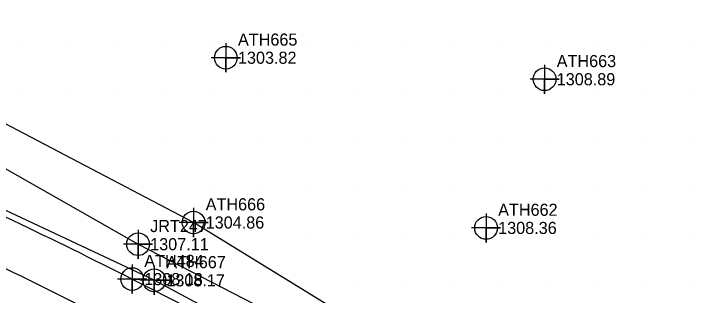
# Model space of a CAD drawing. Extents: x 1234484 to 1235382, y 695050 to 695510.
# Drawn here: x 1235159.5 to 1235304, y 695247.7 to 695305.7 of the extents above; entities that cross this region are included whole.
import ezdxf

# ---------------------------------------------------------------- set-up
doc = ezdxf.new("R2010")
doc.units = 0
for name, color, linetype in [('Exist DTM Breakline', 7, 'Continuous'), ('Exist DTM Breakline Cogo Elevation', 7, 'Continuous'), ('Exist DTM Breakline Cogo Number', 7, 'Continuous'), ('Exist DTM Breakline Cogo Point CELL', 7, 'Continuous'), ('Exist DTM Crownline', 7, 'Continuous'), ('Exist DTM QL2 LIDAR Elevation Point', 7, 'Continuous'), ('Exist DTM Regular Point CELL', 7, 'Continuous'), ('Exist DTM Regular Point Cogo Elevation', 7, 'Continuous'), ('Exist DTM Regular Point Cogo Number', 7, 'Continuous'), ('Exist Roads EOP', 7, 'Continuous'), ('Exist Roads EOP Cogo Elevation', 7, 'Continuous'), ('Exist Roads EOP Cogo Number', 7, 'Continuous'), ('Exist Roads EOP Cogo Point CELL', 7, 'Continuous')]:
    doc.layers.add(name, color=color, linetype=linetype)

msp = doc.modelspace()

# ---------------------------------------------------------------- linework, layer by layer
at = {"layer": 'Exist DTM Breakline'}
for points in [[(1235319.256, 695177.55), (1235278.534, 695201.47), (1235237.781, 695224.217), (1235188.481, 695250.698), (1235134.96, 695275.849), (1235082.338, 695295.901), (1235034.938, 695310.723), (1234997.435, 695322.999)], [(1235324.566, 695184.553), (1235284.54, 695210.684), (1235243.923, 695233.555), (1235196.6, 695262.635), (1235143.527, 695290.446), (1235093.587, 695315.971)], [(1235094.433, 695303.192), (1235139.249, 695284.24), (1235185.145, 695258.152), (1235235.18, 695232.365), (1235270.796, 695206.904), (1235315.147, 695184.076)]]:
    msp.add_lwpolyline(points, dxfattribs=at)
at = {"layer": 'Exist DTM Breakline Cogo Point CELL'}
for points in [[(1235196.6, 695265.635), (1235196.6, 695259.635), (1235196.6, 695262.635), (1235199.6, 695262.635), (1235193.6, 695262.635)], [(1235185.145, 695261.152), (1235185.145, 695255.152), (1235185.145, 695258.152), (1235188.145, 695258.152), (1235182.145, 695258.152)], [(1235188.481, 695253.698), (1235188.481, 695247.698), (1235188.481, 695250.698), (1235191.481, 695250.698), (1235185.481, 695250.698)]]:
    msp.add_lwpolyline(points, dxfattribs=at)
for centre in [(1235196.6, 695262.635), (1235185.145, 695258.152), (1235188.481, 695250.698)]:
    msp.add_circle(centre, 2.344, dxfattribs=at)
at = {"layer": 'Exist DTM Crownline'}
msp.add_spline([(1234978.534, 695313.159), (1235028.867, 695302.317), (1235079.475, 695286.154), (1235130.202, 695265.942), (1235178.94, 695242.599), (1235226.8, 695217.474)], degree=3, dxfattribs=at)
at = {"layer": 'Exist DTM QL2 LIDAR Elevation Point'}
for p, q in [((1235160, 695300), (1235160, 695300)), ((1235170, 695300), (1235170, 695300)), ((1235180, 695300), (1235180, 695300)), ((1235190, 695300), (1235190, 695300)), ((1235200, 695300), (1235200, 695300)), ((1235210, 695300), (1235210, 695300)), ((1235220, 695300), (1235220, 695300)), ((1235230, 695300), (1235230, 695300)), ((1235240, 695300), (1235240, 695300)), ((1235250, 695300), (1235250, 695300)), ((1235260, 695300), (1235260, 695300)), ((1235270, 695300), (1235270, 695300)), ((1235280, 695300), (1235280, 695300)), ((1235290, 695300), (1235290, 695300)), ((1235300, 695300), (1235300, 695300)), ((1235160, 695290), (1235160, 695290)), ((1235170, 695290), (1235170, 695290)), ((1235180, 695290), (1235180, 695290)), ((1235190, 695290), (1235190, 695290)), ((1235200, 695290), (1235200, 695290)), ((1235210, 695290), (1235210, 695290)), ((1235220, 695290), (1235220, 695290)), ((1235230, 695290), (1235230, 695290)), ((1235240, 695290), (1235240, 695290)), ((1235250, 695290), (1235250, 695290)), ((1235260, 695290), (1235260, 695290)), ((1235270, 695290), (1235270, 695290)), ((1235280, 695290), (1235280, 695290)), ((1235290, 695290), (1235290, 695290)), ((1235300, 695290), (1235300, 695290)), ((1235180, 695280), (1235180, 695280)), ((1235190, 695280), (1235190, 695280)), ((1235200, 695280), (1235200, 695280)), ((1235210, 695280), (1235210, 695280)), ((1235220, 695280), (1235220, 695280)), ((1235230, 695280), (1235230, 695280)), ((1235240, 695280), (1235240, 695280)), ((1235250, 695280), (1235250, 695280)), ((1235260, 695280), (1235260, 695280)), ((1235270, 695280), (1235270, 695280)), ((1235280, 695280), (1235280, 695280)), ((1235290, 695280), (1235290, 695280)), ((1235300, 695280), (1235300, 695280)), ((1235200, 695270), (1235200, 695270)), ((1235210, 695270), (1235210, 695270)), ((1235220, 695270), (1235220, 695270)), ((1235230, 695270), (1235230, 695270)), ((1235240, 695270), (1235240, 695270)), ((1235250, 695270), (1235250, 695270)), ((1235260, 695270), (1235260, 695270)), ((1235270, 695270), (1235270, 695270)), ((1235280, 695270), (1235280, 695270)), ((1235290, 695270), (1235290, 695270)), ((1235300, 695270), (1235300, 695270)), ((1235220, 695260), (1235220, 695260)), ((1235230, 695260), (1235230, 695260)), ((1235240, 695260), (1235240, 695260)), ((1235250, 695260), (1235250, 695260)), ((1235260, 695260), (1235260, 695260)), ((1235270, 695260), (1235270, 695260)), ((1235280, 695260), (1235280, 695260)), ((1235290, 695260), (1235290, 695260)), ((1235300, 695260), (1235300, 695260)), ((1235230, 695250), (1235230, 695250)), ((1235240, 695250), (1235240, 695250)), ((1235250, 695250), (1235250, 695250)), ((1235260, 695250), (1235260, 695250)), ((1235270, 695250), (1235270, 695250)), ((1235280, 695250), (1235280, 695250)), ((1235290, 695250), (1235290, 695250)), ((1235300, 695250), (1235300, 695250))]:
    msp.add_line(p, q, dxfattribs=at)
at = {"layer": 'Exist DTM Regular Point CELL'}
for points in [[(1235203.263, 695299.642), (1235203.263, 695293.642), (1235203.263, 695296.642), (1235206.263, 695296.642), (1235200.263, 695296.642)], [(1235269.048, 695295.204), (1235269.048, 695289.204), (1235269.048, 695292.204), (1235272.048, 695292.204), (1235266.048, 695292.204)], [(1235256.96, 695264.511), (1235256.96, 695258.511), (1235256.96, 695261.511), (1235259.96, 695261.511), (1235253.96, 695261.511)]]:
    msp.add_lwpolyline(points, dxfattribs=at)
for centre in [(1235203.263, 695296.642), (1235269.048, 695292.204), (1235256.96, 695261.511)]:
    msp.add_circle(centre, 2.344, dxfattribs=at)
at = {"layer": 'Exist Roads EOP'}
for points in [[(1234989.744, 695321.275), (1235032.632, 695310.758), (1235082.97, 695294.625), (1235134.247, 695274.482), (1235183.928, 695250.955), (1235232.115, 695225.68)], [(1234969.592, 695304.589), (1235025.451, 695292.964), (1235076.313, 695277.193), (1235126.218, 695256.569), (1235174.523, 695234.324), (1235222.247, 695208.988)]]:
    msp.add_spline(points, degree=3, dxfattribs=at)
at = {"layer": 'Exist Roads EOP Cogo Point CELL'}
msp.add_lwpolyline([(1235183.928, 695253.955), (1235183.928, 695247.955), (1235183.928, 695250.955), (1235186.928, 695250.955), (1235180.928, 695250.955)], dxfattribs=at)
msp.add_circle((1235183.928, 695250.955), 2.344, dxfattribs=at)

# ---------------------------------------------------------------- texts
at = {"layer": 'Exist DTM Breakline Cogo Elevation'}
for s, p in [('1304.86', (1235199.1, 695261.385)), ('1307.11', (1235187.645, 695256.902)), ('1308.17', (1235190.981, 695249.448))]:
    msp.add_text(s, height=2.5, dxfattribs=at).set_placement(p)
at = {"layer": 'Exist DTM Breakline Cogo Number'}
for s, p in [('ATH666', (1235199.1, 695265.135)), ('JRT247', (1235187.645, 695260.652)), ('ATH667', (1235190.981, 695253.198))]:
    msp.add_text(s, height=2.5, dxfattribs=at).set_placement(p)
at = {"layer": 'Exist DTM Regular Point Cogo Elevation'}
for s, p in [('1303.82', (1235205.763, 695295.392)), ('1308.89', (1235271.548, 695290.954)), ('1308.36', (1235259.46, 695260.261))]:
    msp.add_text(s, height=2.5, dxfattribs=at).set_placement(p)
at = {"layer": 'Exist DTM Regular Point Cogo Number'}
for s, p in [('ATH665', (1235205.763, 695299.142)), ('ATH663', (1235271.548, 695294.704)), ('ATH662', (1235259.46, 695264.011))]:
    msp.add_text(s, height=2.5, dxfattribs=at).set_placement(p)
at = {"layer": 'Exist Roads EOP Cogo Elevation'}
msp.add_text('1308.18', height=2.5, dxfattribs=at).set_placement((1235186.428, 695249.705))
at = {"layer": 'Exist Roads EOP Cogo Number'}
msp.add_text('ATH484', height=2.5, dxfattribs=at).set_placement((1235186.428, 695253.455))

doc.saveas('drawing.dxf')
